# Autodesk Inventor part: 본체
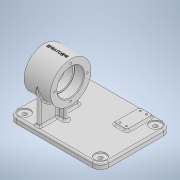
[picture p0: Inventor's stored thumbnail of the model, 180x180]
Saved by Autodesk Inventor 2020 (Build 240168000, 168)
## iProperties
Created: 2024-04
Part Number: 본체
Material: 일반
Document SubType Name: Modeling
Designer: oem
Density: 1 g/cm^3
Appearance: 기본값
Author: jhkim
Sending System: Autodesk Inventor 2025
Preprocessor: ST-DEVELOPER v20
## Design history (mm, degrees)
feature "솔리드1"
node "솔리드2"
